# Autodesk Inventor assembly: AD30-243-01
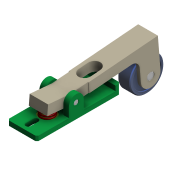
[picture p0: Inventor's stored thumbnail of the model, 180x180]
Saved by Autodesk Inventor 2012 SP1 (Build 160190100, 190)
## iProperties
Created: 2006-03
Part Number: AD30-243-01
Description: DETENT ASSEMBLY
Document SubType Name: Assembly
Designer: t_munrn
Title: DETENT ASM
Author: t_munrn
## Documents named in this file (9)
- D:\AOTC\Autodesk Inventor 2012 Essential for New Users\Autodesk Inventor 2012 Essentials - Project Files\Learning\Workspace\Sub-Assemblies\detent-01.iam
- D:\AOTC\Autodesk Inventor 2012 Essential for New Users\Autodesk Inventor 2012 Essentials - Project Files\Learning\Workspace\Parts\detent bracket.ipt
- D:\AOTC\Autodesk Inventor 2012 Essential for New Users\Autodesk Inventor 2012 Essentials - Project Files\Learning\Workspace\Parts\detent pivot mount.ipt
- D:\AOTC\Autodesk Inventor 2012 Essential for New Users\Autodesk Inventor 2012 Essentials - Project Files\Learning\Workspace\Libraries\Content Center Files\en-US\BA97DF0F-B3F9-031B-C86A-A432CA559196.ipt
- D:\AOTC\Autodesk Inventor 2012 Essential for New Users\Autodesk Inventor 2012 Essentials - Project Files\Learning\Workspace\Libraries\Content Center Files\en-US\9ECBB5A1-AADB-6BAA-27F0-96D7996E1213.ipt
- D:\AOTC\Autodesk Inventor 2012 Essential for New Users\Autodesk Inventor 2012 Essentials - Project Files\Learning\Workspace\Parts\detent roller.ipt
- D:\AOTC\Autodesk Inventor 2012 Essential for New Users\Autodesk Inventor 2012 Essentials - Project Files\Learning\Workspace\Parts\LC-038E-6.ipt
- D:\AOTC\Autodesk Inventor 2012 Essential for New Users\Autodesk Inventor 2012 Essentials - Project Files\Learning\Workspace\Parts\detent roller-01.ipt
- D:\AOTC\Autodesk Inventor 2012 Essential for New Users\Autodesk Inventor 2012 Essentials - Project Files\Learning\Workspace\Sub-Assemblies\detent.iam
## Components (6 placed, 6 different names)
1. detent pivot mount:1 — Insert:1, Insert:3, Flush:2, Flush:3, Mate:3
2. Pin - Hardened Ground Production Dowel - 3/16 x 1/2:1 — Insert:2, Mate:2
3. Pin - Hardened Ground Production Dowel - 1/8 x 3/4:1 — Insert:1
4. detent bracket:1 — Insert:2, Insert:3
5. detent roller-01:1 — Flush:2, Mate:2
6. LC-038E-6:1 — Flush:3, Mate:3
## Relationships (7: Insert 3, Flush 2, Mate 2)
- Insert:1: detent pivot mount:1 ↔ Pin - Hardened Ground Production Dowel - 1/8 x 3/4:1
- Insert:2: Pin - Hardened Ground Production Dowel - 3/16 x 1/2:1 ↔ detent bracket:1
- Insert:3: detent pivot mount:1 ↔ detent bracket:1
- Flush:2: detent pivot mount:1 ↔ detent roller-01:1
- Mate:2: Pin - Hardened Ground Production Dowel - 3/16 x 1/2:1 ↔ detent roller-01:1
- Flush:3: detent pivot mount:1 ↔ LC-038E-6:1
- Mate:3: detent pivot mount:1 ↔ LC-038E-6:1
